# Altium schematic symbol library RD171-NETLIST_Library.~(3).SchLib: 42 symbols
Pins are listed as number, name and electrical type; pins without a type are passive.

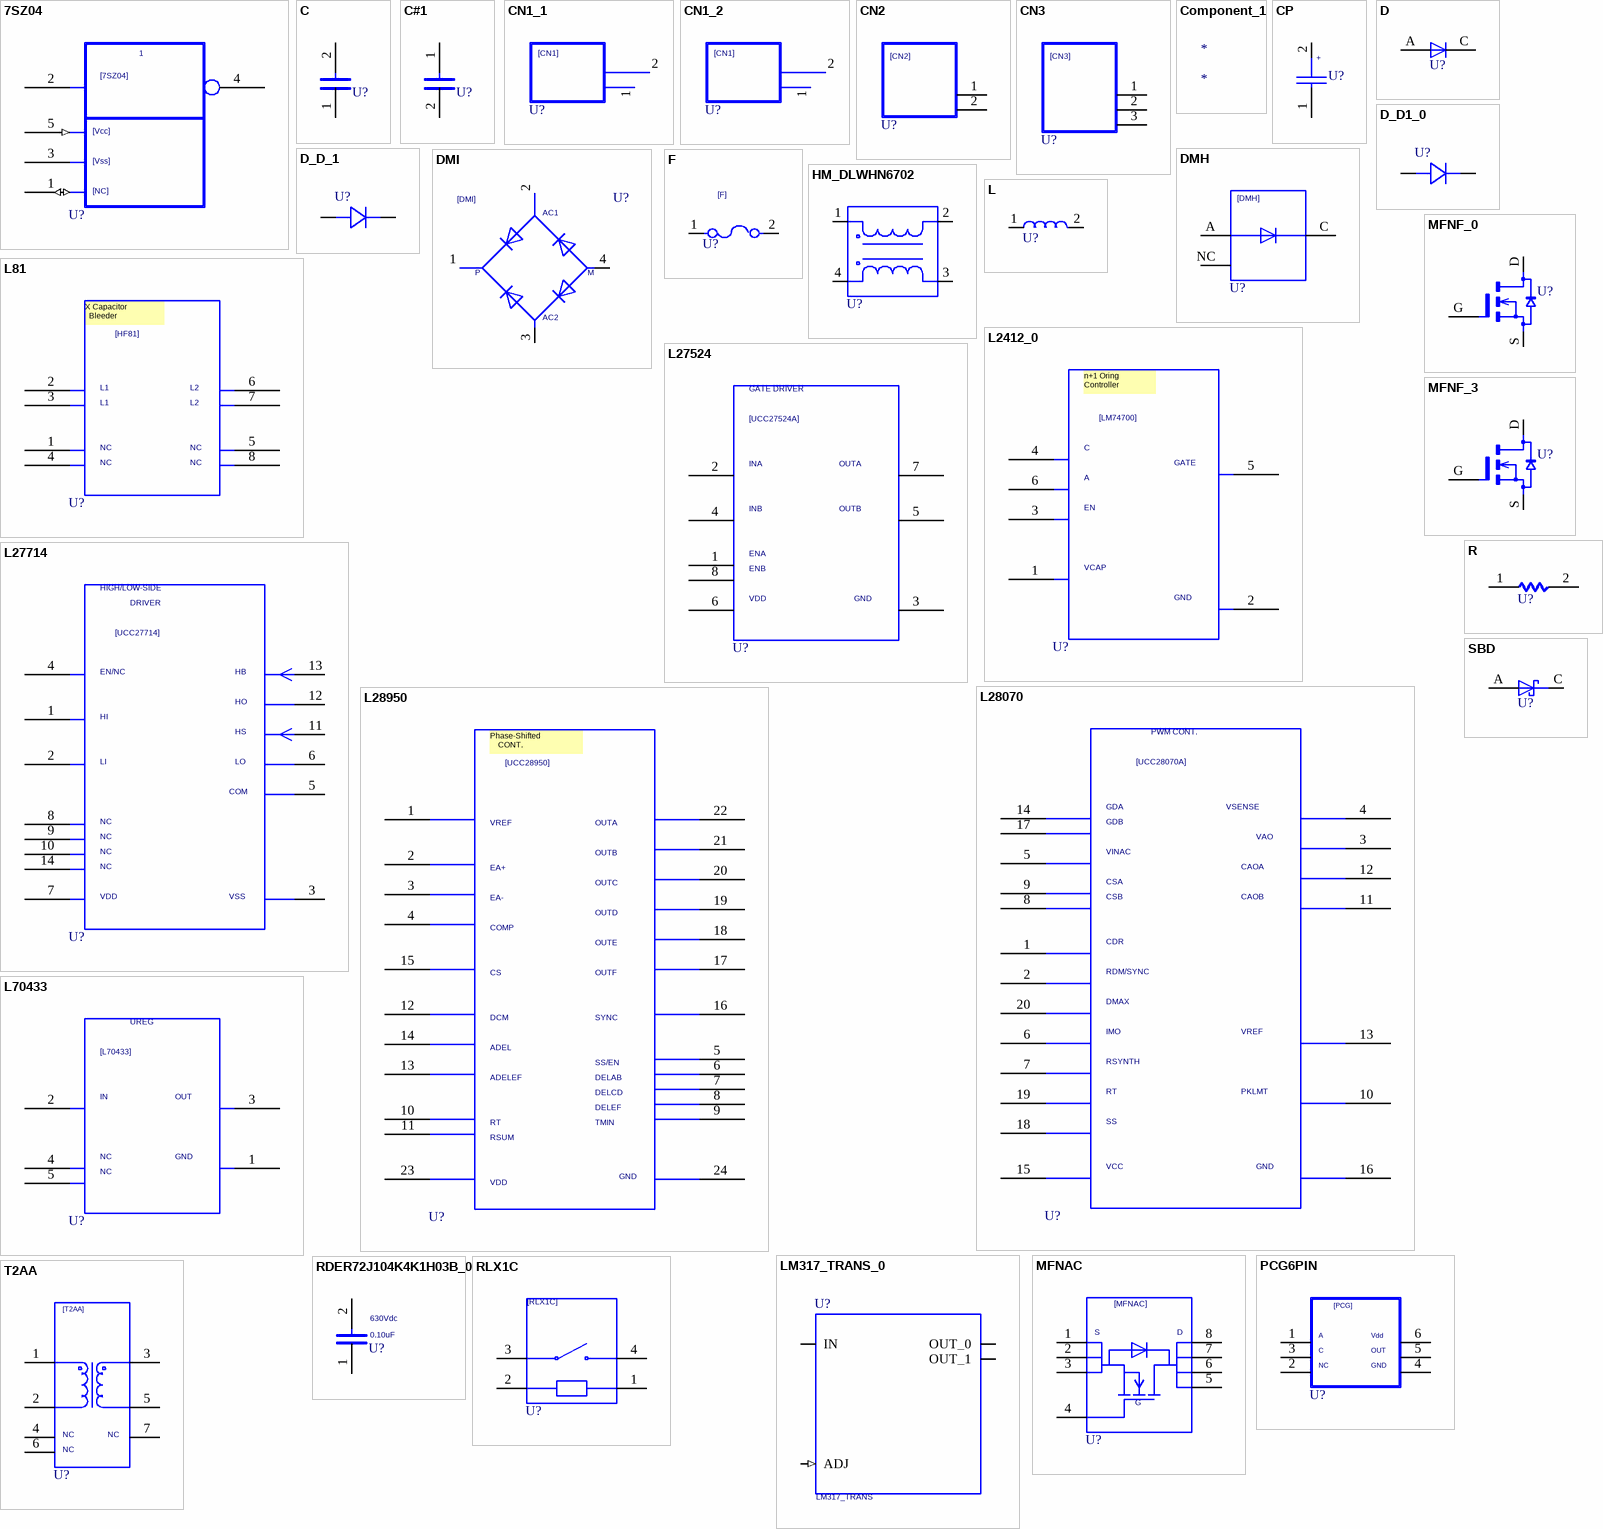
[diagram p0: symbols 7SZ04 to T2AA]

## 7SZ04
designator U?  (value not drawn)
UPDATEUSER: t5459927; UPDATETIME: 13:53:59; SAVECOUNT: 2; TIME: 16:40:05; SAVEAREA0: -20564,-28567,44956,1635; ORIGINALSYMBOLORIGIN: (0,0); Altium-Right: 100; Altium-Bottom: 110
pins: 1 (io), 2, 3, 4, 5 (in)

## C
designator U?  (value not drawn)
ORIGINALSYMBOLORIGIN: (0,0); TIME: 16:40:04; UPDATEUSER: t5459927; SAVECOUNT: 1; Altium-Right: 20; Altium-Bottom: 10
pins: 1, 2

## C#1
designator U?, comment C  (value not drawn)
ORIGINALSYMBOLORIGIN: (0,0); TIME: 16:40:04; UPDATEUSER: t5459927; SAVECOUNT: 1; Altium-Right: 20; Altium-Bottom: 10
pins: 1 2, 2 1

## CN1_1
designator U?, comment CN1  (value not drawn)
PARTNAME: CN1_1; ORIGINALSYMBOLORIGIN: (0,0); TIME: 16:40:05; UPDATEUSER: t5459927; SAVECOUNT: 1; Altium-Right: 80; Altium-Bottom: 40
pins: 1, 2

## CN1_2
designator U?, comment CN1  (value not drawn)
PARTNAME: CN1_2; ORIGINALSYMBOLORIGIN: (0,0); TIME: 16:40:05; UPDATEUSER: t5459927; SAVECOUNT: 1; Altium-Right: 80; Altium-Bottom: 40
pins: 1, 2

## CN2
designator U?  (value not drawn)
ORIGINALSYMBOLORIGIN: (0,0); TIME: 16:40:05; UPDATEUSER: t5459927; SAVECOUNT: 1; Altium-Right: 50; Altium-Bottom: 60
pins: 1, 2

## CN3
designator U?  (value not drawn)
ORIGINALSYMBOLORIGIN: (0,0); TIME: 16:40:05; UPDATEUSER: t5459927; SAVECOUNT: 1; Altium-Right: 50; Altium-Bottom: 70
pins: 1, 2, 3

## Component_1
designator *

## CP
designator U?  (value not drawn)
UPDATEUSER: t5459927; UPDATETIME: 16:40:04; SAVECOUNT: 1; SAVEAREA0: -1450,-153,20294,13055; ORIGINALSYMBOLORIGIN: (0,0); Altium-Right: 20
pins: 1, 2

## D
designator U?  (value not drawn)
UPDATEUSER: t5459927; UPDATETIME: 16:40:05; SAVECOUNT: 1; SAVEAREA0: -225,-91,12804,7836; ORIGINALSYMBOLORIGIN: (0,0); Altium-Right: 10; Altium-Bottom: 20
pins: A, C

## D_D1_0
designator U?  (value not drawn)
PSPICETEMPLATE: X^@REFDES %1 %2 @MODEL; TIME: 16:40:05; UPDATEUSER: t5459927; SAVECOUNT: 1; OriginalSymbolOrigin: (0,0); Altium-Right: 30; Altium-Bottom: 20
simulation model D_D1_0
pins: A, C

## D_D_1
designator U?  (value not drawn)
PSPICETEMPLATE: X^@REFDES %1 %2 @MODEL; TIME: 16:40:05; UPDATEUSER: t5459927; SAVECOUNT: 1; OriginalSymbolOrigin: (0,0); Altium-Right: 30; Altium-Bottom: 20
simulation model D_D_1
pins: A, C

## DMH
designator U?  (value not drawn)
UPDATEUSER: t5459927; UPDATETIME: 16:40:05; SAVECOUNT: 1; SAVEAREA0: -4931,-287,27399,20979; ORIGINALSYMBOLORIGIN: (0,0); Altium-Right: 50; Altium-Bottom: 60
pins: A, C, NC

## DMI
designator U?  (value not drawn)
UPDATEUSER: t5459927; UPDATETIME: 16:40:05; SAVECOUNT: 1; SAVEAREA0: -7762,-358,32649,26224; ORIGINALSYMBOLORIGIN: (0,0); Altium-Right: 90
pins: 1, 2, 3, 4

## F
designator U?  (value not drawn)
ORIGINALSYMBOLORIGIN: (0,0); TIME: 16:40:04; UPDATEUSER: t5459927; SAVECOUNT: 1; Altium-Right: 40; Altium-Bottom: 20
pins: 1, 2

## HM_DLWHN6702
designator U?, comment HM-DLWHN6702  (value not drawn)
UPDATEUSER: t5459927; UPDATETIME: 16:40:05; DEVICENAME: DLW21HN670SQ2; SAVECOUNT: 1; SAVEAREA0: -21350,-26515,41553,39372; ORIGINALSYMBOLORIGIN: (0,0); Altium-Right: 60
pins: 1 (io), 2 (io), 3 (io), 4 (io)

## L
designator U?  (value not drawn)
ORIGINALSYMBOLORIGIN: (0,0); TIME: 16:40:05; UPDATEUSER: t5459927; SAVECOUNT: 1; Altium-Right: 30; Altium-Bottom: 20
pins: 1, 2

## L81
designator U?  (value not drawn)
UPDATEUSER: t5459927; UPDATETIME: 12:05:59; SAVECOUNT: 2; TIME: 16:40:04; SAVEAREA0: -25132,-33687,51942,1841; ORIGINALSYMBOLORIGIN: (0,0); Altium-Right: 110; Altium-Bottom: 130
pins: 1, 2, 3, 4, 5, 6, 7, 8

## L2412_0
designator U?, comment L2412  (value not drawn)
PARTNAME: L2412_0; UPDATEUSER: t5459927; UPDATETIME: 09:34:25; SAVECOUNT: 2; TIME: 16:40:05; SAVEAREA0: -38879,-46643,67840,2550; ORIGINALSYMBOLORIGIN: (0,0); Altium-Right: 120; Altium-Bottom: 180
pins: 1 8, 2 4, 3 2, 4 6, 5, 6 7

## L27524
designator U?  (value not drawn)
UPDATEUSER: t5459927; UPDATETIME: 12:06:53; SAVECOUNT: 2; TIME: 16:40:04; SAVEAREA0: -37147,-44052,63643,2408; ORIGINALSYMBOLORIGIN: (0,0); Altium-Right: 110; Altium-Bottom: 170
pins: 1, 2, 3, 4, 5, 6, 7, 8

## L27714
designator U?  (value not drawn)
UPDATEUSER: t5459927; UPDATETIME: 14:42:01; SAVECOUNT: 2; TIME: 16:40:04; SAVEAREA0: -43740,-59600,92622,3258; ORIGINALSYMBOLORIGIN: (7620,0); Altium-Right: 150; Altium-Bottom: 230
pins: 1, 2, 3, 4, 5, 6, 7, 8, 9, 10, 11, 12, 13, 14

## L28070
designator U?  (value not drawn)
UPDATEUSER: t5459927; UPDATETIME: 12:08:13; SAVECOUNT: 2; TIME: 16:40:04; SAVEAREA0: -70831,-61057,118891,26398; ORIGINALSYMBOLORIGIN: (0,0); Altium-Right: 200; Altium-Bottom: 320
pins: 1, 2, 3, 4, 5, 6, 7, 8, 9, 10, 11, 12, 13, 14, 15, 16, 17, 18, 19, 20

## L28950
designator U?  (value not drawn)
UPDATEUSER: t5459927; UPDATETIME: 13:37:27; SAVECOUNT: 2; TIME: 16:40:04; SAVEAREA0: -41645,-82886,84834,-24583; ORIGINALSYMBOLORIGIN: (0,0); Altium-Right: 180; Altium-Bottom: 320
pins: 1, 2, 3, 4, 5, 6, 7, 8, 9, 10, 11, 12, 13, 14, 15, 16, 17, 18, 19, 20, 21, 22, 23, 24

## L70433
designator U?  (value not drawn)
UPDATEUSER: t5459927; UPDATETIME: 09:35:05; SAVECOUNT: 2; TIME: 16:40:04; SAVEAREA0: -25132,-24804,51942,10724; ORIGINALSYMBOLORIGIN: (0,0); Altium-Right: 110; Altium-Bottom: 130
pins: 1, 2, 3, 4, 5

## LM317_TRANS_0
designator U?, comment LM317_TRANS
ALTERNATE PARTNUMBER: LM317DCY; PARTNAME: LM317_TRANS_0; PARTNUMBER: LM317DCYR; MANUFACTURER: Texas Instruments; PIN_COUNT: 4; SYMBOLCREATER: Altium; DEVICESINPACKAGE: 1; ISHETEROGENEOUS: False; DEVICEDESIGNATOR: A; DEVICENUMBERING: Alpha; PSPICETEMPLATE: X^@REFDES %IN %ADJ %OUT_0 %OUT_1 @MODEL; ORIGINALSYMBOLORIGIN: (0,0); COMPTYPE: IC; TIME: 16:40:05; UPDATEUSER: t5459927; Altium-Right: 110; Altium-Bottom: 120
simulation model LM317_TRANS_0
pins: ADJ (in), IN, OUT_0, OUT_1

## MFNAC
designator U?  (value not drawn)
UPDATEUSER: t5459927; UPDATETIME: 16:40:05; SAVECOUNT: 1; SAVEAREA0: -10143,-336,37609,28718; ORIGINALSYMBOLORIGIN: (0,0); Altium-Right: 70; Altium-Bottom: 90
pins: 1, 2, 3, 4, 5, 6, 7, 8

## MFNF_0
designator U?, comment MFNF  (value not drawn)
PARTNAME: MFNF_0; SAVEAREA0: -7027,-292,21786,15988; ORIGINALSYMBOLORIGIN: (0,0); SAVECOUNT: 1; TIME: 16:40:05; UPDATEUSER: t5459927; Altium-Right: 40
pins: D, G, S

## MFNF_3
designator U?, comment MFNF  (value not drawn)
PARTNAME: MFNF_3; SAVEAREA0: -7027,-292,21786,15988; ORIGINALSYMBOLORIGIN: (0,0); SAVECOUNT: 1; TIME: 16:40:05; UPDATEUSER: t5459927; Altium-Right: 40
pins: D, G, S

## PCG6PIN
designator U?  (value not drawn)
UPDATEUSER: t5459927; UPDATETIME: 16:40:04; SAVECOUNT: 1; SAVEAREA0: -4197,-437,28946,21425; ORIGINALSYMBOLORIGIN: (0,0); Altium-Right: 60
pins: 1, 2, 3, 4, 5, 6

## R
designator U?  (value not drawn)
ORIGINALSYMBOLORIGIN: (0,0); TIME: 16:40:04; UPDATEUSER: t5459927; SAVECOUNT: 1; Altium-Right: 20
pins: 1, 2

## RDER72J104K4K1H03B_0
designator U?  VAL1: 0.10uF  VAL2: 630Vdc  (hidden comment: RDER72J104K4K1H03B_0)
TIME: 16:40:05; UPDATEUSER: t5459927; SAVECOUNT: 1; OriginalSymbolOrigin: (0,0); Altium-Right: 20; Altium-Bottom: 10
pins: 1, 2

## RLX1C
designator U?  (value not drawn)
SAVEAREA0: -13510,-13356,28127,5837; ORIGINALSYMBOLORIGIN: (0,0); SAVECOUNT: 2; TIME: 16:40:05; UPDATEUSER: t5459927; UPDATETIME: 09:35:32; Altium-Right: 60; Altium-Bottom: 70
pins: 1, 2, 3, 4

## SBD
designator U?  (value not drawn)
UPDATEUSER: t5459927; UPDATETIME: 16:40:05; SAVECOUNT: 1; SAVEAREA0: -4630,-153,17114,13055; ORIGINALSYMBOLORIGIN: (0,0); Altium-Right: 20
pins: A, C

## T2AA
designator U?  (value not drawn)
UPDATEUSER: t5459927; UPDATETIME: 16:40:04; SAVECOUNT: 1; SAVEAREA0: -20981,-344,43891,33349; ORIGINALSYMBOLORIGIN: (0,0); Altium-Right: 50; Altium-Bottom: 110
pins: 1, 2, 3, 4, 5 4, 6, 7

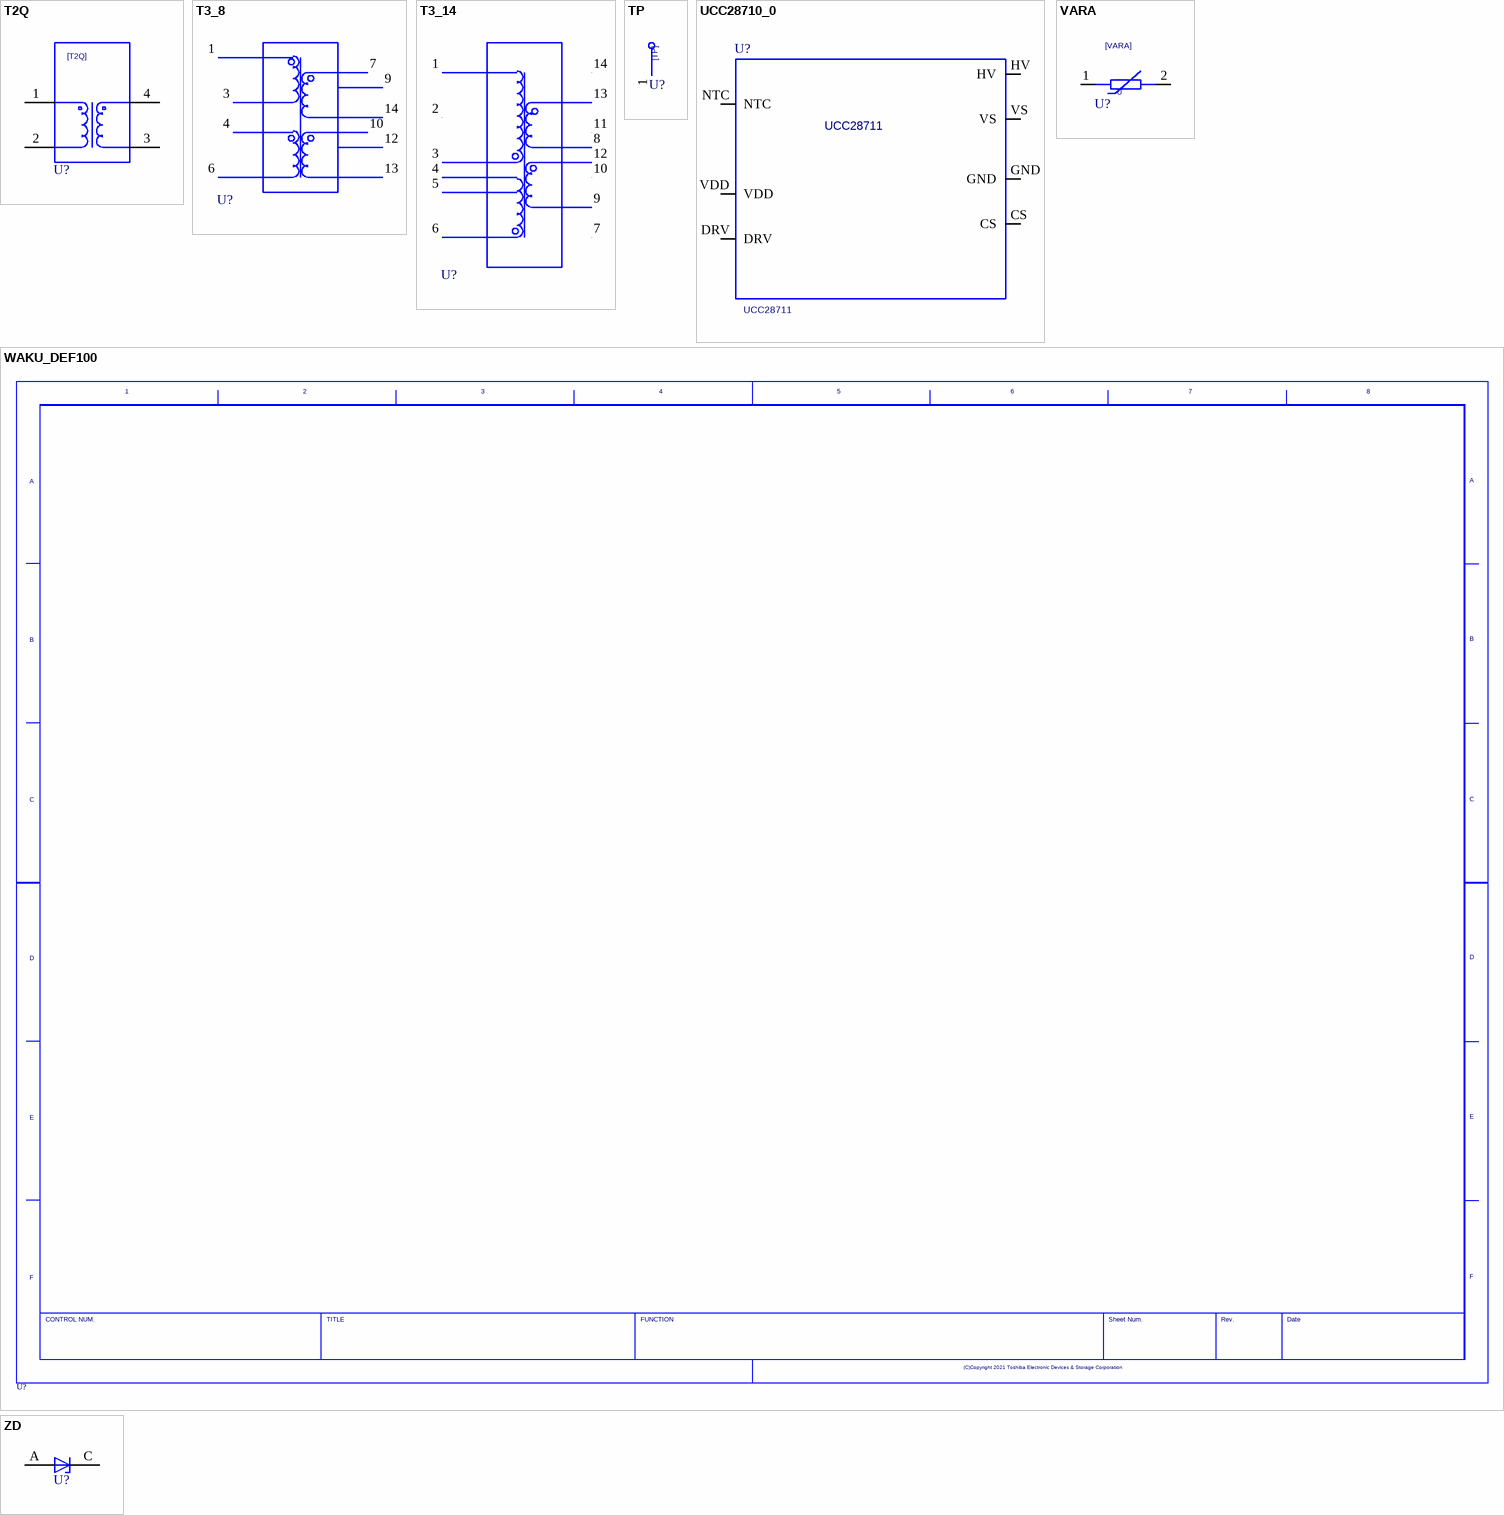
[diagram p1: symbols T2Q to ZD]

## T2Q
designator U?  (value not drawn)
ORIGINALSYMBOLORIGIN: (0,0); TIME: 16:40:05; UPDATEUSER: t5459927; SAVECOUNT: 1; Altium-Right: 50; Altium-Bottom: 80
pins: 1, 2, 3, 4

## T3_8
designator U?, comment T3_12V67A  (value not drawn)
PARTNAME: T3_8; UPDATEUSER: t5459927; UPDATETIME: 13:36:25; SAVECOUNT: 5; TIME: 16:40:06; SAVEAREA0: -24757,-40079,44442,10653; ORIGINALSYMBOLORIGIN: (-7620,0); Altium-Right: 110; Altium-Bottom: 100
pins: 1, 3, 4, 6, 7, 9, 10, 12, 13, 14

## T3_14
designator U?, comment T3_12V67A  (value not drawn)
PARTNAME: T3_14; UPDATEUSER: t5459927; UPDATETIME: 14:07:07; SAVECOUNT: 2; TIME: 16:40:06; SAVEAREA0: -40003,-38869,48929,2125; ORIGINALSYMBOLORIGIN: (-7620,0); Altium-Right: 100; Altium-Bottom: 150
pins: 1 6, 2, 3 6, 4 6, 5 6, 6, 7, 8 5, 9 3, 10, 11, 12 4, 13 6, 14

## TP
designator U?  (value not drawn)
UPDATEUSER: t5459927; UPDATETIME: 16:40:05; SAVECOUNT: 1; SAVEAREA0: -242,-92,12810,7836; ORIGINALSYMBOLORIGIN: (0,0); Altium-Right: 20; Altium-Bottom: 30
pins: 1

## UCC28710_0
designator U?, comment UCC28711
PARTNAME: UCC28710_0; PSPICETEMPLATE: X^@REFDES %CS %VS %CBC %DRV %VDD %GND %HV @MODEL; TIME: 16:40:05; UPDATEUSER: t5459927; UPDATETIME: 14:22:21; SAVECOUNT: 2; SAVEAREA0: -30042,-41524,74477,2202; OriginalSymbolOrigin: (0,0); Altium-Right: 180; Altium-Bottom: 160
simulation model UCC28710_0
pins: CS (io), DRV (io), GND (io), HV (io), NTC (io), VDD (io), VS (io)

## VARA
designator U?  (value not drawn)
UPDATEUSER: t5459927; UPDATETIME: 16:40:05; SAVECOUNT: 1; SAVEAREA0: -9950,-8554,25168,13619; ORIGINALSYMBOLORIGIN: (0,0); Altium-Right: 40; Altium-Bottom: 20
pins: 1, 2

## WAKU_DEF100
designator U?  (value not drawn)
PLOTTIME: HH:MM; SAVEAREA0: 287539,-9995,346305,33088; TIME: 14:30:25; UPDATEUSER: t5459927; UPDATETIME: 11:13:42; SAVECOUNT: 6; OriginalSymbolOrigin: (10160,284480); Altium-Right: 1570; Altium-Bottom: 1070

## ZD
designator U?  (value not drawn)
UPDATEUSER: t5459927; UPDATETIME: 16:40:05; SAVECOUNT: 1; SAVEAREA0: -4630,-153,17114,13055; ORIGINALSYMBOLORIGIN: (0,0); Altium-Right: 10; Altium-Bottom: 20
pins: A, C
